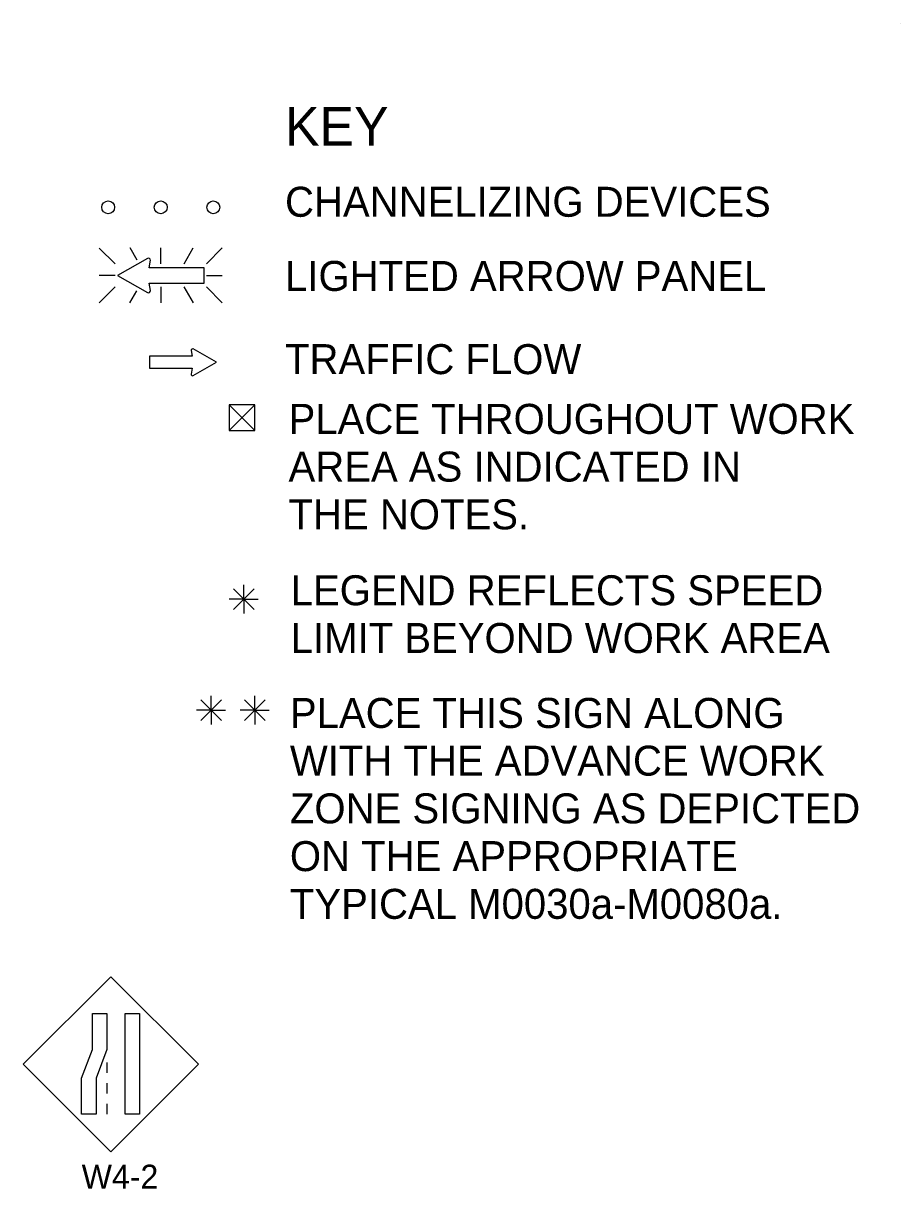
# Model space of a CAD drawing. Extents: x 16590 to 19508, y 5703 to 6974.
# Drawn here: x 18180.4 to 18452.5, y 6569.4 to 6930.8 of the extents above; entities that cross this region are included whole.
import ezdxf

# ---------------------------------------------------------------- set-up
doc = ezdxf.new("R2010")
doc.units = 0
for name, color, linetype in [('BORDER', 7, 'Continuous'), ('MT_SCRATCH_LEVEL_E', 7, 'Continuous'), ('TRAFFIC_SIGNS_PR', 7, 'Continuous'), ('TYPICAL_TEXT_DIMEN_EX', 7, 'Continuous'), ('TYPICAL_TEXT_DIMEN_PR', 7, 'Continuous')]:
    doc.layers.add(name, color=color, linetype=linetype)

msp = doc.modelspace()

# ---------------------------------------------------------------- linework, layer by layer
at = {"layer": 'BORDER'}
msp.add_line((18452.55, 6930.8), (18452.55, 6930.8), dxfattribs=at)
msp.add_line((18452.55, 6930.8), (18452.55, 6930.8), dxfattribs=at)
at = {"layer": 'MT_SCRATCH_LEVEL_E'}
for p, q in [((18232.77, 6827.55), (18219.52, 6827.55)), ((18219.52, 6827.55), (18219.52, 6823.81)), ((18232.46, 6829.33), (18232.77, 6827.55)), ((18240.38, 6825.7), (18233.14, 6829.81)), ((18219.52, 6823.81), (18232.77, 6823.81)), ((18232.77, 6823.81), (18232.46, 6822.03)), ((18233.14, 6821.55), (18240.38, 6825.7))]:
    msp.add_line(p, q, dxfattribs=at)
for centre, start, end in [((18232.92, 6829.4), 60.4248, 189.9638), ((18232.92, 6821.96), 170.0362, 299.7731)]:
    msp.add_arc(centre, 0.463, start, end, dxfattribs=at)
at = {"layer": 'TRAFFIC_SIGNS_PR'}
for p, q in [((18203.97, 6861.12), (18208.9, 6856.19)), ((18215.73, 6857.31), (18213.52, 6861.13)), ((18223.05, 6856.19), (18223.05, 6861.13)), ((18230.29, 6856.19), (18233.14, 6861.13)), ((18237.2, 6856.19), (18242.14, 6861.13)), ((18208.9, 6852.64), (18203.97, 6852.64)), ((18237.2, 6852.64), (18242.14, 6852.64)), ((18203.97, 6844.15), (18208.9, 6849.08)), ((18223.05, 6849.08), (18223.05, 6844.15)), ((18233.18, 6844.15), (18230.33, 6849.08)), ((18237.2, 6849.08), (18242.14, 6844.15)), ((18213.48, 6844.15), (18215.59, 6847.81)), ((18207.58, 6635.16), (18180.42, 6608.01)), ((18234.73, 6608.01), (18207.58, 6635.16)), ((18180.42, 6608.01), (18207.58, 6580.86)), ((18206.33, 6608.5), (18206.33, 6605.3)), ((18207.58, 6580.86), (18234.73, 6608.01)), ((18206.33, 6602.1), (18206.33, 6598.9)), ((18206.33, 6595.7), (18206.33, 6592.5))]:
    msp.add_line(p, q, dxfattribs=at)
for points in [[(18218.98, 6857.91), (18209.69, 6852.64), (18218.98, 6847.32)], [(18219.85, 6847.94), (18219.45, 6850.21), (18236.47, 6850.21), (18236.47, 6855.01), (18219.45, 6855.01), (18219.86, 6857.3)]]:
    msp.add_lwpolyline(points, dxfattribs=at)
for points in [[(18206.33, 6623.75), (18206.33, 6612.57), (18202.99, 6603.68), (18202.99, 6592.5), (18198.49, 6592.5), (18198.49, 6603.68), (18201.84, 6612.57), (18201.84, 6623.75)], [(18216.47, 6623.75), (18216.47, 6592.5), (18211.97, 6592.5), (18211.97, 6623.75)]]:
    msp.add_lwpolyline(points, close=True, dxfattribs=at)
for centre in [(18206.76, 6873.75), (18223.06, 6873.75), (18239.36, 6873.75)]:
    msp.add_circle(centre, 2, dxfattribs=at)
for centre, radius, start, end in [((18219.27, 6857.39), 0.598, 350.7308, 118.8916), ((18219.26, 6847.84), 0.597, 241.4833, 9.9593)]:
    msp.add_arc(centre, radius, start, end, dxfattribs=at)
at = {"layer": 'TYPICAL_TEXT_DIMEN_PR'}
for p, q in [((18244.24, 6812.5), (18252.24, 6804.5)), ((18244.24, 6804.5), (18252.24, 6812.5)), ((18245.61, 6755.42), (18251.99, 6749.05)), ((18251.99, 6755.42), (18245.61, 6749.05)), ((18248.8, 6752.24), (18248.8, 6756.69)), ((18248.8, 6752.24), (18244.27, 6752.24)), ((18248.8, 6752.24), (18251.99, 6752.24)), ((18248.8, 6752.24), (18253.28, 6752.24)), ((18248.8, 6752.24), (18248.8, 6747.74)), ((18238.7, 6717.84), (18238.7, 6722.29)), ((18252.2, 6717.84), (18252.2, 6722.29)), ((18235.51, 6721.02), (18241.89, 6714.65)), ((18241.89, 6721.02), (18235.51, 6714.65)), ((18249.02, 6721.02), (18255.39, 6714.65)), ((18255.39, 6721.02), (18249.02, 6714.65)), ((18238.7, 6717.84), (18234.17, 6717.84)), ((18238.7, 6717.84), (18241.89, 6717.84)), ((18238.7, 6717.84), (18243.18, 6717.84)), ((18238.7, 6717.84), (18238.7, 6713.34)), ((18252.2, 6717.84), (18247.67, 6717.84)), ((18252.2, 6717.84), (18255.39, 6717.84)), ((18252.2, 6717.84), (18256.68, 6717.84)), ((18252.2, 6717.84), (18252.2, 6713.34))]:
    msp.add_line(p, q, dxfattribs=at)
msp.add_lwpolyline([(18244.24, 6812.5), (18244.24, 6804.5), (18252.24, 6804.5), (18252.24, 6812.5)], close=True, dxfattribs=at)
msp.add_open_spline([(18340.39, 6742.62), (18340.41, 6742.62), (18340.42, 6742.62), (18340.42, 6742.62)], degree=2, dxfattribs=at)

# ---------------------------------------------------------------- texts
at = {"layer": 'TRAFFIC_SIGNS_PR'}
msp.add_text('W4-2', height=7.44, dxfattribs=at).set_placement((18198.53, 6569.42))
at = {"layer": 'TYPICAL_TEXT_DIMEN_EX'}
for s, height, p in [('KEY', 12, (18261.6, 6892.86)), ('CHANNELIZING DEVICES', 9.3, (18261.6, 6870.81)), ('LIGHTED ARROW PANEL', 9.3, (18261.6, 6847.81)), ('TRAFFIC FLOW', 9.3, (18261.6, 6822.01)), ('PLACE THROUGHOUT WORK', 9.3, (18262.69, 6803.49)), ('AREA AS INDICATED IN', 9.3, (18262.69, 6788.69)), ('THE NOTES.', 9.3, (18262.69, 6773.89)), ('LEGEND REFLECTS SPEED', 9.3, (18263.35, 6750.34)), ('LIMIT BEYOND WORK AREA', 9.3, (18263.35, 6735.54)), ('PLACE THIS SIGN ALONG', 9.3, (18263.11, 6712.3)), ('WITH THE ADVANCE WORK', 9.3, (18263.11, 6697.5)), ('ZONE SIGNING AS DEPICTED', 9.3, (18263.11, 6682.7)), ('ON THE APPROPRIATE', 9.3, (18263.11, 6667.9)), ('TYPICAL M0030a-M0080a.', 9.3, (18263.11, 6653.1))]:
    msp.add_text(s, height=height, dxfattribs=at).set_placement(p)

doc.saveas('drawing.dxf')
